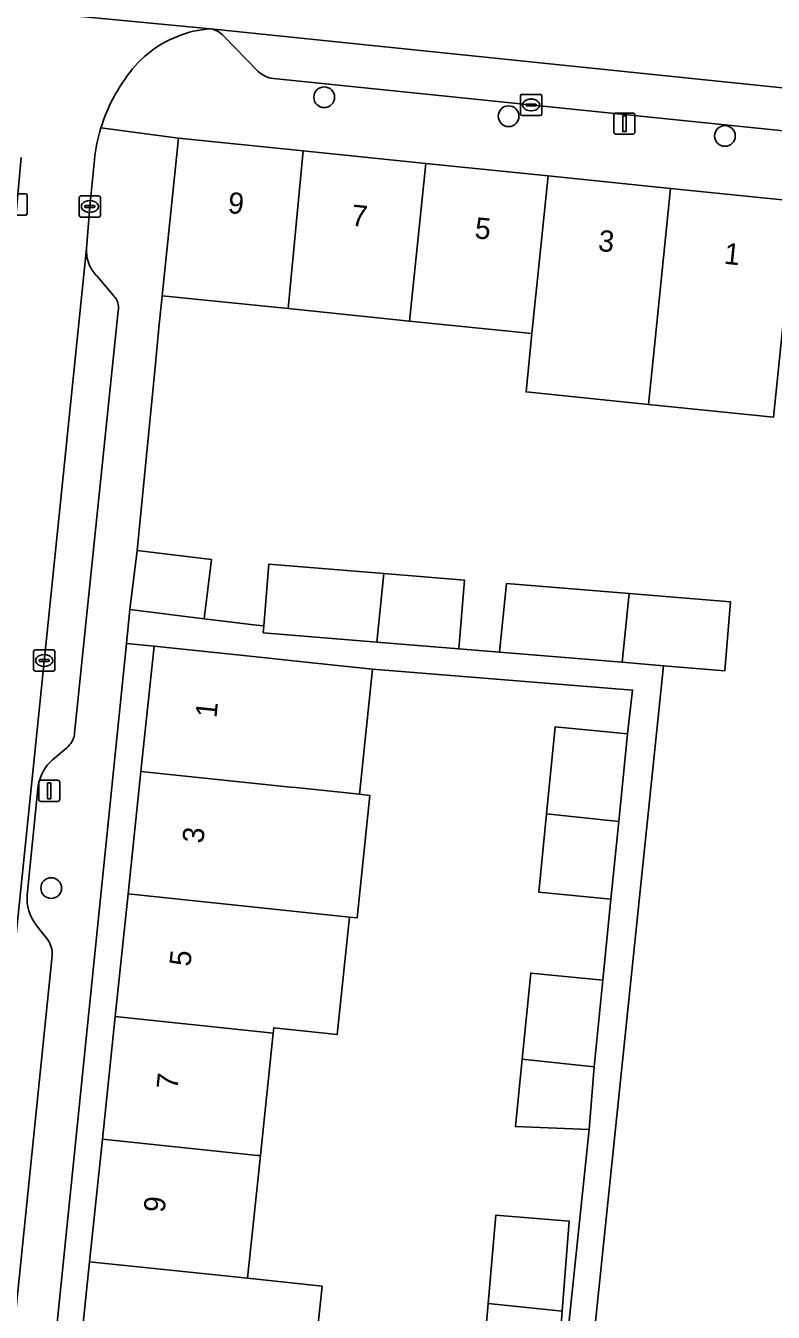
# Model space of a CAD drawing. Extents: x 160856 to 161310, y 384024 to 384878.
# Drawn here: x 161193.9 to 161229.2, y 384613.9 to 384674.6 of the extents above; entities that cross this region are included whole.
import ezdxf

# ---------------------------------------------------------------- set-up
doc = ezdxf.new("R2010")
doc.units = 0
for name, color, linetype in [('IMGEO_Boom', 7, 'Continuous'), ('IMGEO_Erf', 7, 'Continuous'), ('IMGEO_Kolk', 7, 'Continuous'), ('IMGEO_Lichtmast', 7, 'Continuous'), ('IMGEO_Muur', 7, 'Continuous'), ('IMGEO_Pand', 7, 'Continuous'), ('IMGEO_Pand_nummerreeks', 7, 'Continuous'), ('IMGEO_Parkeervlak_open', 7, 'Continuous'), ('IMGEO_Rijbaan_lokaal_open', 7, 'Continuous'), ('IMGEO_Voetpad_open', 7, 'Continuous')]:
    doc.layers.add(name, color=color, linetype=linetype)

msp = doc.modelspace()

# ---------------------------------------------------------------- linework, layer by layer
at = {"layer": 'IMGEO_Boom'}
for centre in [(161207.999, 384671.269), (161216.698, 384670.374), (161226.905, 384669.441), (161195.119, 384633.943)]:
    msp.add_circle(centre, 0.489, dxfattribs=at)
at = {"layer": 'IMGEO_Erf'}
for points in [[(161229.192, 384656.167), (161223.296, 384656.771), (161217.52, 384657.363), (161217.802, 384660.116), (161212.027, 384660.707), (161206.293, 384661.294), (161200.356, 384661.902), (161200.2, 384660.38), (161200.035, 384658.689), (161199.176, 384649.88), (161202.684, 384649.445), (161202.338, 384646.652), (161204.811, 384646.346), (161205.154, 384646.318), (161205.393, 384649.235), (161210.807, 384648.791), (161214.616, 384648.478), (161214.349, 384645.233), (161216.262, 384645.076), (161216.594, 384648.315), (161222.381, 384647.84), (161227.17, 384647.447), (161226.904, 384644.202), (161224.003, 384644.44), (161218.539, 384591.638)], [(161218.084, 384599.409), (161220.506, 384622.55), (161217.022, 384622.699), (161217.338, 384625.871), (161217.742, 384629.93), (161221.145, 384629.591), (161221.526, 384633.418), (161218.123, 384633.757), (161218.491, 384637.447), (161218.9, 384641.556), (161222.303, 384641.217), (161222.551, 384643.288), (161210.284, 384644.277), (161209.666, 384638.372), (161210.154, 384638.321), (161209.548, 384632.536), (161209.196, 384632.572), (161208.616, 384627.035), (161205.622, 384627.349), (161205.596, 384627.101), (161204.99, 384621.315), (161204.384, 384615.53), (161207.897, 384615.162), (161207.291, 384609.377)]]:
    msp.add_lwpolyline(points, dxfattribs=at)
for points in [[(161196.928, 384616.311), (161197.534, 384622.096), (161198.14, 384627.882), (161198.746, 384633.667), (161199.352, 384639.452), (161199.971, 384645.357), (161198.667, 384645.49), (161192.741, 384587.382), (161193.885, 384587.265), (161194.504, 384593.171), (161195.11, 384598.956), (161195.716, 384604.741), (161196.322, 384610.526)], [(161215.734, 384614.342), (161216.101, 384618.503), (161219.562, 384618.231), (161219.228, 384613.976), (161218.943, 384610.349), (161215.407, 384610.627)]]:
    msp.add_lwpolyline(points, close=True, dxfattribs=at)
at = {"layer": 'IMGEO_Kolk'}
for p, q in [((161217.26, 384670.48), (161217.26, 384671.332)), ((161217.335, 384671.406), (161218.187, 384671.406)), ((161217.748, 384671.186), (161217.773, 384671.186)), ((161218.261, 384671.332), (161218.261, 384670.48)), ((161218.187, 384670.406), (161217.335, 384670.406)), ((161217.519, 384670.9), (161217.519, 384670.912)), ((161217.957, 384670.863), (161217.559, 384670.863)), ((161217.562, 384670.949), (161217.96, 384670.949)), ((161217.771, 384670.626), (161217.746, 384670.626)), ((161218.003, 384670.912), (161218.003, 384670.9)), ((161193.066, 384666.709), (161193.918, 384666.709)), ((161193.992, 384666.635), (161193.992, 384665.783)), ((161196.441, 384665.687), (161196.441, 384666.539)), ((161196.516, 384666.613), (161197.368, 384666.613)), ((161196.7, 384666.107), (161196.7, 384666.119)), ((161196.743, 384666.156), (161197.141, 384666.156)), ((161196.929, 384666.393), (161196.954, 384666.393)), ((161197.184, 384666.119), (161197.184, 384666.107)), ((161197.442, 384666.539), (161197.442, 384665.687)), ((161193.918, 384665.709), (161193.066, 384665.709)), ((161197.368, 384665.613), (161196.516, 384665.613)), ((161197.138, 384666.07), (161196.74, 384666.07)), ((161196.952, 384665.833), (161196.927, 384665.833)), ((161194.288, 384644.259), (161194.288, 384645.111)), ((161194.363, 384645.185), (161195.215, 384645.185)), ((161194.776, 384644.965), (161194.801, 384644.965)), ((161195.289, 384645.111), (161195.289, 384644.259)), ((161194.547, 384644.679), (161194.547, 384644.691)), ((161194.985, 384644.642), (161194.587, 384644.642)), ((161194.59, 384644.728), (161194.988, 384644.728)), ((161194.799, 384644.405), (161194.774, 384644.405)), ((161195.031, 384644.691), (161195.031, 384644.679)), ((161195.215, 384644.185), (161194.363, 384644.185))]:
    msp.add_line(p, q, dxfattribs=at)
for points in [[(161217.26, 384670.48), (161217.26, 384671.332)], [(161217.335, 384671.406), (161218.187, 384671.406)], [(161218.261, 384671.332), (161218.261, 384670.48)], [(161218.187, 384670.406), (161217.335, 384670.406)], [(161193.066, 384666.709), (161193.918, 384666.709)], [(161193.992, 384666.635), (161193.992, 384665.783)], [(161196.441, 384665.687), (161196.441, 384666.539)], [(161196.516, 384666.613), (161197.368, 384666.613)], [(161197.442, 384666.539), (161197.442, 384665.687)], [(161193.918, 384665.709), (161193.066, 384665.709)], [(161197.368, 384665.613), (161196.516, 384665.613)], [(161194.288, 384644.259), (161194.288, 384645.111)], [(161194.363, 384645.185), (161195.215, 384645.185)], [(161195.289, 384645.111), (161195.289, 384644.259)], [(161195.215, 384644.185), (161194.363, 384644.185)]]:
    msp.add_lwpolyline(points, dxfattribs=at)
for centre, radius, start, end in [((161217.337, 384671.33), 0.0765, 91.55205, 178.44795), ((161217.337, 384671.33), 0.0765, 91.55205, 178.44795), ((161218.185, 384671.33), 0.0765, 1.55205, 88.44795), ((161218.185, 384671.33), 0.0765, 1.55205, 88.44795), ((161217.337, 384670.482), 0.0765, 181.55205, 268.44795), ((161217.337, 384670.482), 0.0765, 181.55205, 268.44795), ((161217.559, 384670.909), 0.0403, 85.87752, 175.75265), ((161217.556, 384670.899), 0.0366, 178.93798, 274.71019), ((161217.96, 384670.906), 0.043, 264.86636, 352.45326), ((161217.964, 384670.911), 0.0386, 1.73085, 96.63898), ((161218.185, 384670.482), 0.0765, 271.55205, 358.44795), ((161218.185, 384670.482), 0.0765, 271.55205, 358.44795), ((161193.916, 384666.633), 0.0765, 1.55205, 88.44795), ((161193.916, 384666.633), 0.0765, 1.55205, 88.44795), ((161196.518, 384666.537), 0.0765, 91.55205, 178.44795), ((161196.518, 384666.537), 0.0765, 91.55205, 178.44795), ((161196.74, 384666.116), 0.0403, 85.87752, 175.75265), ((161196.737, 384666.106), 0.0366, 178.93798, 274.71019), ((161197.141, 384666.113), 0.043, 264.86636, 352.45326), ((161197.145, 384666.118), 0.0386, 1.73085, 96.63898), ((161197.366, 384666.537), 0.0765, 1.55205, 88.44795), ((161197.366, 384666.537), 0.0765, 1.55205, 88.44795), ((161193.916, 384665.785), 0.0765, 271.55205, 358.44795), ((161193.916, 384665.785), 0.0765, 271.55205, 358.44795), ((161196.518, 384665.689), 0.0765, 181.55205, 268.44795), ((161196.518, 384665.689), 0.0765, 181.55205, 268.44795), ((161197.366, 384665.689), 0.0765, 271.55205, 358.44795), ((161197.366, 384665.689), 0.0765, 271.55205, 358.44795), ((161194.365, 384645.109), 0.0765, 91.55205, 178.44795), ((161194.365, 384645.109), 0.0765, 91.55205, 178.44795), ((161195.213, 384645.109), 0.0765, 1.55205, 88.44795), ((161195.213, 384645.109), 0.0765, 1.55205, 88.44795), ((161194.365, 384644.261), 0.0765, 181.55205, 268.44795), ((161194.365, 384644.261), 0.0765, 181.55205, 268.44795), ((161194.587, 384644.688), 0.0403, 85.87752, 175.75265), ((161194.584, 384644.678), 0.0366, 178.93798, 274.71019), ((161194.988, 384644.685), 0.043, 264.86636, 352.45326), ((161194.992, 384644.69), 0.0386, 1.73085, 96.63898), ((161195.213, 384644.261), 0.0765, 271.55205, 358.44795), ((161195.213, 384644.261), 0.0765, 271.55205, 358.44795)]:
    msp.add_arc(centre, radius, start, end, dxfattribs=at)
for centre, major_axis, ratio, start_param, end_param in [((161217.747, 384670.906), (-0.387, 0.002), 0.722429, 4.712389, 7.853982), ((161217.772, 384670.906), (-0.39, 0.002), 0.717154, 1.570796, 4.712389), ((161196.928, 384666.113), (-0.387, 0.002), 0.722429, 4.712389, 7.853982), ((161196.953, 384666.113), (-0.39, 0.002), 0.717154, 1.570796, 4.712389), ((161194.775, 384644.685), (-0.387, 0.002), 0.722429, 4.712389, 7.853982), ((161194.8, 384644.685), (-0.39, 0.002), 0.717154, 1.570796, 4.712389)]:
    msp.add_ellipse(centre, major_axis=major_axis, ratio=ratio, start_param=start_param, end_param=end_param, dxfattribs=at)
at = {"layer": 'IMGEO_Lichtmast'}
for p, q in [((161221.667, 384669.624), (161221.667, 384670.424)), ((161221.667, 384670.424), (161221.667, 384669.624)), ((161221.767, 384670.524), (161222.557, 384670.524)), ((161222.557, 384670.524), (161221.767, 384670.524)), ((161222.657, 384670.424), (161222.657, 384669.624)), ((161222.657, 384669.624), (161222.657, 384670.424)), ((161222.557, 384669.524), (161221.767, 384669.524)), ((161221.767, 384669.524), (161222.557, 384669.524)), ((161194.53, 384638.133), (161194.53, 384638.933)), ((161194.53, 384638.933), (161194.53, 384638.133)), ((161194.63, 384639.033), (161195.42, 384639.033)), ((161195.42, 384639.033), (161194.63, 384639.033)), ((161195.52, 384638.933), (161195.52, 384638.133)), ((161195.52, 384638.133), (161195.52, 384638.933)), ((161195.42, 384638.033), (161194.63, 384638.033)), ((161194.63, 384638.033), (161195.42, 384638.033))]:
    msp.add_line(p, q, dxfattribs=at)
for points in [[(161222.087, 384670.399), (161222.237, 384670.399), (161222.237, 384669.649), (161222.087, 384669.649), (161222.087, 384670.399)], [(161194.95, 384638.908), (161195.1, 384638.908), (161195.1, 384638.158), (161194.95, 384638.158), (161194.95, 384638.908)]]:
    msp.add_lwpolyline(points, dxfattribs=at)
for centre, start, end in [((161221.767, 384670.424), 90, 180), ((161221.767, 384670.424), 90, 180), ((161222.557, 384670.424), 0, 90), ((161222.557, 384670.424), 360, 90), ((161221.767, 384669.624), 180, 270), ((161221.767, 384669.624), 180, 270), ((161222.557, 384669.624), 270, 0), ((161222.557, 384669.624), 270, 0), ((161194.63, 384638.933), 90, 180), ((161194.63, 384638.933), 90, 180), ((161195.42, 384638.933), 0, 90), ((161195.42, 384638.933), 360, 90), ((161194.63, 384638.133), 180, 270), ((161194.63, 384638.133), 180, 270), ((161195.42, 384638.133), 270, 0), ((161195.42, 384638.133), 270, 0)]:
    msp.add_arc(centre, 0.1, start, end, dxfattribs=at)
at = {"layer": 'IMGEO_Muur'}
msp.add_lwpolyline([(161200.2, 384660.38), (161200.035, 384658.689)], dxfattribs=at)
at = {"layer": 'IMGEO_Pand'}
for points in [[(161207.014, 384668.74), (161201.118, 384669.343), (161200.356, 384661.902), (161206.293, 384661.294)], [(161212.789, 384668.149), (161207.014, 384668.74), (161206.293, 384661.294), (161212.027, 384660.707)], [(161212.789, 384668.149), (161212.027, 384660.707), (161217.802, 384660.116), (161218.564, 384667.558)], [(161223.296, 384656.771), (161223.578, 384659.525), (161224.34, 384666.966), (161218.564, 384667.558), (161217.802, 384660.116), (161217.52, 384657.363)], [(161223.296, 384656.771), (161229.192, 384656.167), (161229.474, 384658.921), (161229.727, 384661.39), (161230.236, 384666.363), (161224.34, 384666.966), (161223.578, 384659.525)], [(161202.684, 384649.445), (161199.176, 384649.88), (161198.83, 384647.087), (161202.338, 384646.652)], [(161210.807, 384648.791), (161205.393, 384649.235), (161205.154, 384646.318), (161205.127, 384645.991), (161210.475, 384645.551)], [(161210.807, 384648.791), (161210.475, 384645.551), (161214.349, 384645.233), (161214.616, 384648.478)], [(161222.381, 384647.84), (161216.594, 384648.315), (161216.262, 384645.076), (161222.05, 384644.601)], [(161227.17, 384647.447), (161222.381, 384647.84), (161222.05, 384644.601), (161224.003, 384644.44), (161226.904, 384644.202)], [(161210.284, 384644.277), (161207.427, 384644.576), (161204.944, 384644.836), (161199.971, 384645.357), (161199.352, 384639.452), (161206.416, 384638.712), (161206.665, 384638.686), (161206.808, 384638.671), (161209.666, 384638.372)], [(161222.303, 384641.217), (161218.9, 384641.556), (161218.491, 384637.447), (161221.892, 384637.091)], [(161210.154, 384638.321), (161209.666, 384638.372), (161206.808, 384638.671), (161206.665, 384638.686), (161206.416, 384638.712), (161199.352, 384639.452), (161198.746, 384633.667), (161206.059, 384632.901), (161206.202, 384632.886), (161209.196, 384632.572), (161209.548, 384632.536)], [(161221.892, 384637.091), (161218.491, 384637.447), (161218.123, 384633.757), (161221.526, 384633.418)], [(161209.196, 384632.572), (161206.202, 384632.886), (161206.059, 384632.901), (161198.746, 384633.667), (161198.14, 384627.882), (161205.454, 384627.116), (161205.596, 384627.101), (161205.622, 384627.349), (161208.616, 384627.035)], [(161221.145, 384629.591), (161217.742, 384629.93), (161217.338, 384625.871), (161220.739, 384625.515)], [(161198.14, 384627.882), (161197.534, 384622.096), (161204.848, 384621.33), (161204.99, 384621.315), (161205.596, 384627.101), (161205.454, 384627.116)], [(161220.739, 384625.515), (161217.338, 384625.871), (161217.022, 384622.699), (161220.506, 384622.55)], [(161196.928, 384616.311), (161204.243, 384615.545), (161204.384, 384615.53), (161204.99, 384621.315), (161204.848, 384621.33), (161197.534, 384622.096)], [(161215.734, 384614.342), (161219.228, 384613.976), (161219.562, 384618.231), (161216.101, 384618.503)], [(161204.384, 384615.53), (161204.243, 384615.545), (161196.928, 384616.311), (161196.322, 384610.526), (161203.637, 384609.76), (161203.778, 384609.745), (161207.291, 384609.377), (161207.897, 384615.162)], [(161219.228, 384613.976), (161215.734, 384614.342), (161215.407, 384610.627), (161218.943, 384610.349)]]:
    msp.add_lwpolyline(points, close=True, dxfattribs=at)
at = {"layer": 'IMGEO_Parkeervlak_open'}
for points in [[(161251.394, 384669.225), (161251.411, 384669.458), (161202.637, 384674.492)], [(161203.244, 384674.161), (161204.89, 384672.49)], [(161205.608, 384672.152), (161248.369, 384667.771)], [(161192.485, 384604.745), (161195.161, 384630.759), (161195.165, 384630.858), (161195.16, 384630.957), (161195.146, 384631.055), (161195.124, 384631.151), (161195.093, 384631.245), (161195.054, 384631.336), (161195.007, 384631.423), (161194.957, 384631.498), (161194.432, 384632.184), (161194.415, 384632.206), (161194.306, 384632.361), (161194.212, 384632.525), (161194.133, 384632.697), (161194.07, 384632.876), (161194.022, 384633.059), (161193.992, 384633.246), (161193.978, 384633.435), (161193.981, 384633.624), (161194.495, 384638.636), (161194.509, 384638.766), (161194.542, 384638.942), (161194.591, 384639.115), (161194.655, 384639.283), (161194.734, 384639.445), (161194.827, 384639.599), (161194.934, 384639.744), (161195.053, 384639.878), (161195.183, 384640.002), (161195.855, 384640.57), (161195.923, 384640.631), (161195.985, 384640.698), (161196.042, 384640.77), (161196.091, 384640.847), (161196.134, 384640.928), (161196.169, 384641.012), (161196.196, 384641.099), (161196.215, 384641.188), (161196.224, 384641.249), (161198.278, 384661.196), (161198.288, 384661.267), (161198.291, 384661.34), (161198.288, 384661.412), (161198.279, 384661.483), (161198.263, 384661.554), (161198.241, 384661.622), (161198.213, 384661.689), (161198.179, 384661.752), (161198.14, 384661.813), (161198.095, 384661.869), (161198.046, 384661.922), (161198.036, 384661.931), (161197.285, 384662.82), (161197.248, 384662.858), (161197.148, 384662.975), (161197.058, 384663.1), (161196.98, 384663.233), (161196.915, 384663.372), (161196.862, 384663.516), (161196.822, 384663.665), (161196.795, 384663.816), (161196.782, 384663.969), (161196.783, 384664.123), (161190.514, 384603.047)]]:
    msp.add_lwpolyline(points, dxfattribs=at)
for centre, radius, start, end in [((161202.494, 384673.507), 0.995, 41.06944, 81.72287), ((161205.731, 384673.345), 1.199, 225.47043, 264.11195)]:
    msp.add_arc(centre, radius, start, end, dxfattribs=at)
at = {"layer": 'IMGEO_Rijbaan_lokaal_open'}
for points in [[(161135.61, 384681.376), (161139.001, 384680.825), (161143.066, 384680.491), (161143.188, 384680.479), (161185.816, 384676.135), (161185.922, 384676.125), (161187.912, 384675.92), (161202.637, 384674.492), (161251.411, 384669.458), (161251.394, 384669.225), (161252.77, 384669.111), (161253.501, 384675.224), (161252.277, 384675.194), (161251.143, 384675.297), (161239.508, 384676.544), (161229.088, 384676.847)], [(161202.637, 384674.492), (161187.912, 384675.92)], [(161193.706, 384668.431), (161193.353, 384664.564), (161193.316, 384664.397), (161193.265, 384664.233), (161193.255, 384664.211), (161188.222, 384615.309), (161188.224, 384615.295), (161188.23, 384615.137), (161188.221, 384614.979), (161187.046, 384603.398), (161190.514, 384603.047), (161196.783, 384664.123)], [(161196.783, 384664.123), (161196.942, 384666.113), (161197.158, 384668.322)]]:
    msp.add_lwpolyline(points, dxfattribs=at)
for centre, radius, start, end in [((161203.061, 384669.179), 5.348, 111.84423, 146.77979), ((161202.859, 384669.809), 4.688, 92.71078, 112.41656), ((161205.143, 384667.474), 8.029, 144.73801, 162.91966), ((161205.229, 384667.452), 8.118, 162.95031, 173.84667)]:
    msp.add_arc(centre, radius, start, end, dxfattribs=at)
at = {"layer": 'IMGEO_Voetpad_open'}
for points in [[(161204.89, 384672.49), (161203.244, 384674.161)], [(161248.369, 384667.771), (161205.608, 384672.152)], [(161187.451, 384523.374), (161188.052, 384529.256), (161188.217, 384530.792), (161188.382, 384532.327), (161187.135, 384532.404), (161192.466, 384584.685), (161192.741, 384587.382), (161198.667, 384645.49), (161198.83, 384647.087), (161199.176, 384649.88), (161200.035, 384658.689), (161200.2, 384660.38), (161200.356, 384661.902), (161201.118, 384669.343), (161197.468, 384669.832)], [(161197.468, 384669.832), (161201.118, 384669.343), (161207.014, 384668.74), (161212.789, 384668.149), (161218.564, 384667.558), (161224.34, 384666.966), (161230.236, 384666.363), (161231.728, 384666.208), (161239.297, 384665.418), (161253.755, 384663.908), (161255.213, 384668.454)], [(161197.158, 384668.322), (161196.942, 384666.113), (161196.783, 384664.123), (161196.782, 384663.969), (161196.795, 384663.816), (161196.822, 384663.665), (161196.862, 384663.516), (161196.915, 384663.372), (161196.98, 384663.233), (161197.058, 384663.1), (161197.148, 384662.975), (161197.248, 384662.858), (161197.285, 384662.82), (161198.036, 384661.931), (161198.046, 384661.922), (161198.095, 384661.869), (161198.14, 384661.813), (161198.179, 384661.752), (161198.213, 384661.689), (161198.241, 384661.622), (161198.263, 384661.554), (161198.279, 384661.483), (161198.288, 384661.412), (161198.291, 384661.34), (161198.288, 384661.267), (161198.278, 384661.196), (161196.224, 384641.249), (161196.215, 384641.188), (161196.196, 384641.099), (161196.169, 384641.012), (161196.134, 384640.928), (161196.091, 384640.847), (161196.042, 384640.77), (161195.985, 384640.698), (161195.923, 384640.631), (161195.855, 384640.57), (161195.183, 384640.002), (161195.053, 384639.878), (161194.934, 384639.744), (161194.827, 384639.599), (161194.734, 384639.445), (161194.655, 384639.283), (161194.591, 384639.115), (161194.542, 384638.942), (161194.509, 384638.766), (161194.495, 384638.636), (161193.981, 384633.624), (161193.978, 384633.435), (161193.992, 384633.246), (161194.022, 384633.059), (161194.07, 384632.876), (161194.133, 384632.697), (161194.212, 384632.525), (161194.306, 384632.361), (161194.415, 384632.206), (161194.432, 384632.184), (161194.957, 384631.498), (161195.007, 384631.423), (161195.054, 384631.336), (161195.093, 384631.245), (161195.124, 384631.151), (161195.146, 384631.055), (161195.16, 384630.957), (161195.165, 384630.858), (161195.161, 384630.759), (161192.485, 384604.745)], [(161218.539, 384591.638), (161224.003, 384644.44), (161222.05, 384644.601), (161216.262, 384645.076), (161214.349, 384645.233), (161210.475, 384645.551), (161205.127, 384645.991), (161205.154, 384646.318), (161204.811, 384646.346), (161202.338, 384646.652), (161198.83, 384647.087), (161198.667, 384645.49), (161199.971, 384645.357), (161204.944, 384644.836), (161207.427, 384644.576), (161210.284, 384644.277), (161222.551, 384643.288), (161222.303, 384641.217), (161221.892, 384637.091), (161221.526, 384633.418), (161221.145, 384629.591), (161220.739, 384625.515), (161220.506, 384622.55), (161218.084, 384599.409)]]:
    msp.add_lwpolyline(points, dxfattribs=at)
for centre, radius, start, end in [((161203.061, 384669.179), 5.348, 111.84423, 146.77979), ((161202.859, 384669.809), 4.688, 92.71078, 112.41656), ((161202.494, 384673.507), 0.995, 41.06944, 81.72287), ((161205.731, 384673.345), 1.199, 225.47043, 264.11195), ((161205.143, 384667.474), 8.029, 144.73801, 162.91966), ((161205.229, 384667.452), 8.118, 162.95031, 173.84667)]:
    msp.add_arc(centre, radius, start, end, dxfattribs=at)

# ---------------------------------------------------------------- texts
at = {"layer": 'IMGEO_Pand_nummerreeks'}
for s, rotation, p in [('9', 354.15583, (161203.422, 384665.811)), ('7', 354.15657, (161209.245, 384665.214)), ('5', 354.15657, (161215.069, 384664.618)), ('3', 354.15657, (161220.892, 384664.022)), ('1', 354.15657, (161226.83, 384663.414)), ('1', 84.01853, (161202.913, 384641.95)), ('3', 84.01853, (161202.292, 384636.027)), ('5', 84.01853, (161201.684, 384630.218)), ('7', 84.01923, (161201.074, 384624.409)), ('9', 84.01923, (161200.466, 384618.599))]:
    msp.add_text(s, height=1, rotation=rotation, dxfattribs=at).set_placement(p)

doc.saveas('drawing.dxf')
